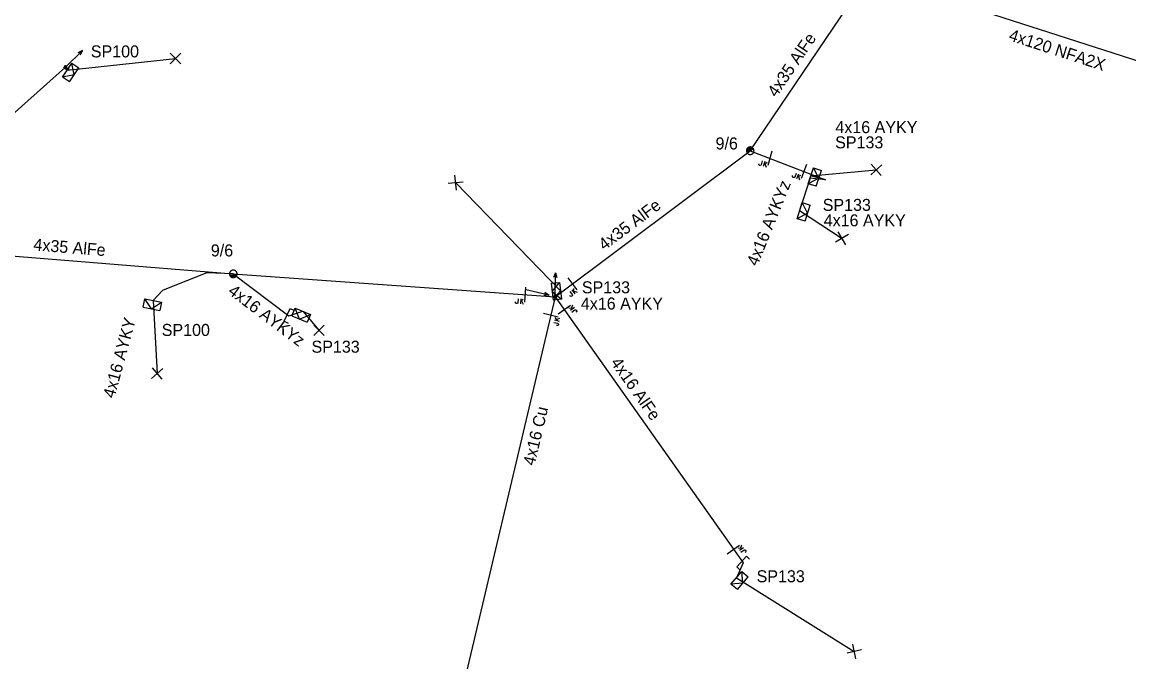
# Model space of a CAD drawing. Extents: x -788458 to -786145, y -1154772 to -1152372.
# Drawn here: x -786452.8 to -786360.6, y -1153548.2 to -1153494.9 of the extents above; entities that cross this region are included whole.
import ezdxf

# ---------------------------------------------------------------- set-up
doc = ezdxf.new("R2010")
doc.units = 0
for name, color, linetype in [('Vrstva 1', 7, 'Continuous'), ('Vrstva 12', 7, 'Continuous'), ('Vrstva 13', 7, 'Continuous'), ('Vrstva 15', 7, 'Continuous'), ('Vrstva 18', 7, 'Continuous'), ('Vrstva 2', 7, 'Continuous'), ('Vrstva 31', 7, 'Continuous'), ('Vrstva 33', 7, 'Continuous'), ('Vrstva 34', 7, 'Continuous'), ('Vrstva 4', 7, 'Continuous'), ('Vrstva 50', 7, 'Continuous'), ('Vrstva 51', 7, 'Continuous'), ('Vrstva 52', 7, 'Continuous'), ('Vrstva 53', 7, 'Continuous'), ('Vrstva 54', 7, 'Continuous'), ('Vrstva 55', 7, 'Continuous'), ('Vrstva 59', 7, 'Continuous'), ('Vrstva 9', 7, 'Continuous')]:
    doc.layers.add(name, color=color, linetype=linetype)

# ---------------------------------------------------------------- blocks, each defined once
blk = doc.blocks.new('NN440')
at = {"layer": 'Vrstva 2'}
for points in [[(0.63, 0), (0.63, 0.06), (0.62, 0.13), (0.6, 0.19), (0.58, 0.25), (0.55, 0.31), (0.51, 0.37), (0.47, 0.42), (0.42, 0.46), (0.37, 0.51), (0.32, 0.54), (0.26, 0.57), (0.2, 0.59), (0.13, 0.61), (0.07, 0.62), (0, 0.63), (-0.06, 0.62), (-0.13, 0.61), (-0.19, 0.59), (-0.26, 0.57), (-0.31, 0.54), (-0.37, 0.51), (-0.42, 0.46), (-0.47, 0.42), (-0.51, 0.37), (-0.54, 0.31), (-0.57, 0.25), (-0.6, 0.19), (-0.62, 0.13), (-0.63, 0.06), (-0.63, 0), (-0.63, -0.07), (-0.62, -0.14), (-0.6, -0.2), (-0.57, -0.26), (-0.54, -0.32), (-0.51, -0.37), (-0.47, -0.43), (-0.42, -0.47), (-0.37, -0.51), (-0.31, -0.55), (-0.26, -0.58), (-0.19, -0.6), (-0.13, -0.62), (-0.06, -0.63), (0, -0.63), (0.07, -0.63), (0.13, -0.62), (0.2, -0.6), (0.26, -0.58), (0.32, -0.55), (0.37, -0.51), (0.42, -0.47), (0.47, -0.43), (0.51, -0.37), (0.55, -0.32), (0.58, -0.26), (0.6, -0.2), (0.62, -0.14), (0.63, -0.07), (0.63, 0)], [(-0.63, 0), (0.63, 0)], [(-0.6, -0.18), (0.57, -0.18)], [(-0.51, -0.32), (0.5, -0.32)], [(-0.37, -0.47), (0.35, -0.47)]]:
    blk.add_lwpolyline(points, dxfattribs=at)
blk = doc.blocks.new('NN560')
at = {"layer": 'Vrstva 2'}
for points in [[(1.999, -0.001), (1.59, 0.141)], [(0, -0.001), (1.999, -0.001)], [(1.999, -0.001), (1.59, -0.134)]]:
    blk.add_lwpolyline(points, dxfattribs=at)
blk = doc.blocks.new('NN840')
at = {"layer": 'Vrstva 15'}
for points in [[(0.003, 0.619), (0.003, -0.631)], [(-0.745, -0.71), (-0.745, -0.66)], [(-0.73, -0.764), (-0.745, -0.71)], [(-0.657, -0.798), (-0.73, -0.764)], [(-0.627, -0.798), (-0.657, -0.798)], [(-0.558, -0.764), (-0.627, -0.798)], [(-0.538, -0.71), (-0.558, -0.764)], [(-0.538, -0.385), (-0.538, -0.71)], [(-0.332, -0.385), (-0.332, -0.798)], [(-0.332, -0.641), (-0.125, -0.385)], [(-0.263, -0.557), (-0.091, -0.798)]]:
    blk.add_lwpolyline(points, dxfattribs=at)
blk = doc.blocks.new('NN565')
at = {"layer": 'Vrstva 2'}
for points in [[(0.015, 0.528), (0.015, 2.528)], [(0.157, 0.937), (0.015, 0.528), (-0.119, 0.937)]]:
    blk.add_lwpolyline(points, dxfattribs=at)
blk = doc.blocks.new('NN800')
at = {"layer": 'Vrstva 1'}
for points in [[(-0.442, 0.442), (0.442, -0.442)], [(-0.442, -0.442), (0.442, 0.442)]]:
    blk.add_lwpolyline(points, dxfattribs=at)
blk = doc.blocks.new('NN630')
at = {"layer": 'Vrstva 9'}
for points in [[(-0.003, -0.7), (-0.703, 0)], [(-0.703, -0.7), (-0.703, 0), (0.697, 0), (0.697, -0.7)], [(-0.703, -0.7), (0.697, -0.7)], [(-0.003, -0.7), (0.697, 0)]]:
    blk.add_lwpolyline(points, dxfattribs=at)
blk = doc.blocks.new('NN500')
at = {"layer": 'Vrstva 2'}
for points in [[(0, -0.24), (0.02, -0.23), (0.05, -0.23), (0.07, -0.22), (0.09, -0.22), (0.12, -0.2), (0.14, -0.19), (0.16, -0.18), (0.17, -0.16), (0.19, -0.14), (0.2, -0.12), (0.21, -0.1), (0.22, -0.07), (0.23, -0.05), (0.23, -0.02), (0.23, 0), (0.23, 0.02), (0.23, 0.05), (0.22, 0.07), (0.21, 0.1), (0.2, 0.12), (0.19, 0.14), (0.17, 0.16), (0.16, 0.17), (0.14, 0.19), (0.12, 0.2), (0.09, 0.21), (0.07, 0.22), (0.05, 0.23), (0.02, 0.23), (0, 0.23), (-0.03, 0.23), (-0.05, 0.23), (-0.07, 0.22), (-0.1, 0.21), (-0.12, 0.2), (-0.14, 0.19), (-0.16, 0.17), (-0.18, 0.16), (-0.19, 0.14), (-0.2, 0.12), (-0.22, 0.1), (-0.22, 0.07), (-0.23, 0.05), (-0.23, 0.02), (-0.24, 0), (-0.23, -0.02), (-0.23, -0.05), (-0.22, -0.07), (-0.22, -0.1), (-0.2, -0.12), (-0.19, -0.14), (-0.18, -0.16), (-0.16, -0.18), (-0.14, -0.19), (-0.12, -0.2), (-0.1, -0.22), (-0.07, -0.22), (-0.05, -0.23), (-0.03, -0.23), (0, -0.24)], [(0, -0.24), (0.02, -0.23), (0.05, -0.23), (0.07, -0.22), (0.09, -0.22), (0.12, -0.2), (0.14, -0.19), (0.16, -0.18), (0.17, -0.16), (0.19, -0.14), (0.2, -0.12), (0.21, -0.1), (0.22, -0.07), (0.23, -0.05), (0.23, -0.02), (0.23, 0), (0.23, 0.02), (0.23, 0.05), (0.22, 0.07), (0.21, 0.1), (0.2, 0.12), (0.19, 0.14), (0.17, 0.16), (0.16, 0.17), (0.14, 0.19), (0.12, 0.2), (0.09, 0.21), (0.07, 0.22), (0.05, 0.23), (0.02, 0.23), (0, 0.23), (-0.03, 0.23), (-0.05, 0.23), (-0.07, 0.22), (-0.1, 0.21), (-0.12, 0.2), (-0.14, 0.19), (-0.16, 0.17), (-0.18, 0.16), (-0.19, 0.14), (-0.2, 0.12), (-0.22, 0.1), (-0.22, 0.07), (-0.23, 0.05), (-0.23, 0.02), (-0.24, 0), (-0.23, -0.02), (-0.23, -0.05), (-0.22, -0.07), (-0.22, -0.1), (-0.2, -0.12), (-0.19, -0.14), (-0.18, -0.16), (-0.16, -0.18), (-0.14, -0.19), (-0.12, -0.2), (-0.1, -0.22), (-0.07, -0.22), (-0.05, -0.23), (-0.03, -0.23), (0, -0.24)], [(0, -0.21), (0.02, -0.2), (0.04, -0.2), (0.06, -0.2), (0.08, -0.19), (0.1, -0.18), (0.12, -0.17), (0.14, -0.15), (0.15, -0.14), (0.16, -0.12), (0.18, -0.1), (0.19, -0.08), (0.19, -0.06), (0.2, -0.04), (0.2, -0.02), (0.2, 0), (0.2, 0.02), (0.2, 0.04), (0.19, 0.06), (0.19, 0.08), (0.18, 0.1), (0.16, 0.12), (0.15, 0.14), (0.14, 0.15), (0.12, 0.17), (0.1, 0.18), (0.08, 0.19), (0.06, 0.19), (0.04, 0.2), (0.02, 0.2), (0, 0.2), (-0.02, 0.2), (-0.04, 0.2), (-0.06, 0.19), (-0.08, 0.19), (-0.1, 0.18), (-0.12, 0.17), (-0.14, 0.15), (-0.15, 0.14), (-0.17, 0.12), (-0.18, 0.1), (-0.19, 0.08), (-0.2, 0.06), (-0.2, 0.04), (-0.21, 0.02), (-0.21, 0), (-0.21, -0.02), (-0.2, -0.04), (-0.2, -0.06), (-0.19, -0.08), (-0.18, -0.1), (-0.17, -0.12), (-0.15, -0.14), (-0.14, -0.15), (-0.12, -0.17), (-0.1, -0.18), (-0.08, -0.19), (-0.06, -0.2), (-0.04, -0.2), (-0.02, -0.2), (0, -0.21)], [(0, -0.18), (0.02, -0.18), (0.04, -0.17), (0.05, -0.17), (0.07, -0.16), (0.09, -0.15), (0.1, -0.14), (0.12, -0.13), (0.13, -0.12), (0.14, -0.1), (0.15, -0.09), (0.16, -0.07), (0.17, -0.05), (0.17, -0.04), (0.17, -0.02), (0.17, 0), (0.17, 0.02), (0.17, 0.04), (0.17, 0.05), (0.16, 0.07), (0.15, 0.09), (0.14, 0.1), (0.13, 0.12), (0.12, 0.13), (0.1, 0.14), (0.09, 0.15), (0.07, 0.16), (0.05, 0.17), (0.04, 0.17), (0.02, 0.17), (0, 0.18), (-0.02, 0.17), (-0.04, 0.17), (-0.06, 0.17), (-0.07, 0.16), (-0.09, 0.15), (-0.1, 0.14), (-0.12, 0.13), (-0.13, 0.12), (-0.14, 0.1), (-0.15, 0.09), (-0.16, 0.07), (-0.17, 0.05), (-0.17, 0.04), (-0.18, 0.02), (-0.18, 0), (-0.18, -0.02), (-0.17, -0.04), (-0.17, -0.05), (-0.16, -0.07), (-0.15, -0.09), (-0.14, -0.1), (-0.13, -0.12), (-0.12, -0.13), (-0.1, -0.14), (-0.09, -0.15), (-0.07, -0.16), (-0.06, -0.17), (-0.04, -0.17), (-0.02, -0.18), (0, -0.18)], [(0, -0.15), (0.01, -0.15), (0.03, -0.14), (0.04, -0.14), (0.06, -0.13), (0.07, -0.13), (0.08, -0.12), (0.1, -0.11), (0.11, -0.1), (0.12, -0.09), (0.13, -0.07), (0.13, -0.06), (0.14, -0.05), (0.14, -0.03), (0.14, -0.02), (0.14, 0), (0.14, 0.01), (0.14, 0.03), (0.14, 0.04), (0.13, 0.06), (0.13, 0.07), (0.12, 0.09), (0.11, 0.1), (0.1, 0.11), (0.08, 0.12), (0.07, 0.13), (0.06, 0.13), (0.04, 0.14), (0.03, 0.14), (0.01, 0.14), (0, 0.15), (-0.02, 0.14), (-0.03, 0.14), (-0.05, 0.14), (-0.06, 0.13), (-0.07, 0.13), (-0.09, 0.12), (-0.1, 0.11), (-0.11, 0.1), (-0.12, 0.09), (-0.13, 0.07), (-0.13, 0.06), (-0.14, 0.04), (-0.14, 0.03), (-0.15, 0.01), (-0.15, 0), (-0.15, -0.02), (-0.14, -0.03), (-0.14, -0.05), (-0.13, -0.06), (-0.13, -0.07), (-0.12, -0.09), (-0.11, -0.1), (-0.1, -0.11), (-0.09, -0.12), (-0.07, -0.13), (-0.06, -0.13), (-0.05, -0.14), (-0.03, -0.14), (-0.02, -0.15), (0, -0.15)], [(0, -0.12), (0.01, -0.12), (0.02, -0.11), (0.03, -0.11), (0.05, -0.11), (0.06, -0.1), (0.07, -0.09), (0.08, -0.09), (0.09, -0.08), (0.09, -0.07), (0.1, -0.06), (0.11, -0.05), (0.11, -0.04), (0.11, -0.02), (0.11, -0.01), (0.12, 0), (0.11, 0.01), (0.11, 0.02), (0.11, 0.04), (0.11, 0.05), (0.1, 0.06), (0.09, 0.07), (0.09, 0.08), (0.08, 0.09), (0.07, 0.09), (0.06, 0.1), (0.05, 0.11), (0.03, 0.11), (0.02, 0.11), (0.01, 0.12), (0, 0.12), (-0.01, 0.12), (-0.03, 0.11), (-0.04, 0.11), (-0.05, 0.11), (-0.06, 0.1), (-0.07, 0.09), (-0.08, 0.09), (-0.09, 0.08), (-0.1, 0.07), (-0.1, 0.06), (-0.11, 0.05), (-0.11, 0.04), (-0.12, 0.02), (-0.12, 0.01), (-0.12, 0), (-0.12, -0.01), (-0.12, -0.02), (-0.11, -0.04), (-0.11, -0.05), (-0.1, -0.06), (-0.1, -0.07), (-0.09, -0.08), (-0.08, -0.09), (-0.07, -0.09), (-0.06, -0.1), (-0.05, -0.11), (-0.04, -0.11), (-0.03, -0.11), (-0.01, -0.12), (0, -0.12)], [(0, -0.09), (0.01, -0.09), (0.02, -0.09), (0.03, -0.08), (0.03, -0.08), (0.04, -0.08), (0.05, -0.07), (0.06, -0.07), (0.06, -0.06), (0.07, -0.05), (0.07, -0.04), (0.08, -0.04), (0.08, -0.03), (0.08, -0.02), (0.09, -0.01), (0.09, 0), (0.09, 0.01), (0.08, 0.02), (0.08, 0.03), (0.08, 0.03), (0.07, 0.04), (0.07, 0.05), (0.06, 0.06), (0.06, 0.06), (0.05, 0.07), (0.04, 0.07), (0.03, 0.08), (0.03, 0.08), (0.02, 0.08), (0.01, 0.09), (0, 0.09), (-0.01, 0.09), (-0.02, 0.08), (-0.03, 0.08), (-0.04, 0.08), (-0.04, 0.07), (-0.05, 0.07), (-0.06, 0.06), (-0.07, 0.06), (-0.07, 0.05), (-0.08, 0.04), (-0.08, 0.03), (-0.08, 0.03), (-0.09, 0.02), (-0.09, 0.01), (-0.09, 0), (-0.09, -0.01), (-0.09, -0.02), (-0.08, -0.03), (-0.08, -0.04), (-0.08, -0.04), (-0.07, -0.05), (-0.07, -0.06), (-0.06, -0.07), (-0.05, -0.07), (-0.04, -0.08), (-0.04, -0.08), (-0.03, -0.08), (-0.02, -0.09), (-0.01, -0.09), (0, -0.09)], [(0, -0.06), (0, -0.06), (0.01, -0.06), (0.02, -0.05), (0.02, -0.05), (0.03, -0.05), (0.03, -0.05), (0.04, -0.04), (0.04, -0.04), (0.05, -0.03), (0.05, -0.03), (0.05, -0.02), (0.05, -0.02), (0.05, -0.01), (0.06, -0.01), (0.06, 0), (0.06, 0.01), (0.05, 0.01), (0.05, 0.02), (0.05, 0.02), (0.05, 0.03), (0.05, 0.03), (0.04, 0.04), (0.04, 0.04), (0.03, 0.05), (0.03, 0.05), (0.02, 0.05), (0.02, 0.05), (0.01, 0.06), (0, 0.06), (0, 0.06), (-0.01, 0.06), (-0.01, 0.06), (-0.02, 0.05), (-0.02, 0.05), (-0.03, 0.05), (-0.03, 0.05), (-0.04, 0.04), (-0.04, 0.04), (-0.05, 0.03), (-0.05, 0.03), (-0.05, 0.02), (-0.06, 0.02), (-0.06, 0.01), (-0.06, 0.01), (-0.06, 0), (-0.06, -0.01), (-0.06, -0.01), (-0.06, -0.02), (-0.05, -0.02), (-0.05, -0.03), (-0.05, -0.03), (-0.04, -0.04), (-0.04, -0.04), (-0.03, -0.05), (-0.03, -0.05), (-0.02, -0.05), (-0.02, -0.05), (-0.01, -0.06), (-0.01, -0.06), (0, -0.06)], [(0, -0.03), (0, -0.03), (0, -0.03), (0.01, -0.03), (0.01, -0.03), (0.01, -0.02), (0.02, -0.02), (0.02, -0.02), (0.02, -0.02), (0.02, -0.02), (0.02, -0.01), (0.02, -0.01), (0.03, -0.01), (0.03, -0.01), (0.03, 0), (0.03, 0), (0.03, 0), (0.03, 0.01), (0.03, 0.01), (0.02, 0.01), (0.02, 0.01), (0.02, 0.02), (0.02, 0.02), (0.02, 0.02), (0.02, 0.02), (0.01, 0.02), (0.01, 0.02), (0.01, 0.03), (0, 0.03), (0, 0.03), (0, 0.03), (0, 0.03), (-0.01, 0.03), (-0.01, 0.03), (-0.01, 0.02), (-0.02, 0.02), (-0.02, 0.02), (-0.02, 0.02), (-0.02, 0.02), (-0.02, 0.02), (-0.03, 0.01), (-0.03, 0.01), (-0.03, 0.01), (-0.03, 0.01), (-0.03, 0), (-0.03, 0), (-0.03, 0), (-0.03, -0.01), (-0.03, -0.01), (-0.03, -0.01), (-0.03, -0.01), (-0.02, -0.02), (-0.02, -0.02), (-0.02, -0.02), (-0.02, -0.02), (-0.02, -0.02), (-0.01, -0.03), (-0.01, -0.03), (-0.01, -0.03), (0, -0.03), (0, -0.03)], [(0.23, 0), (0.7, 0)]]:
    blk.add_lwpolyline(points, dxfattribs=at)
blk = doc.blocks.new('NN510')
at = {"layer": 'Vrstva 2'}
blk.add_lwpolyline([(0.001, 0.002), (0.001, 0.939)], dxfattribs=at)
blk = doc.blocks.new('NN515')
at = {"layer": 'Vrstva 2'}
for points in [[(-0.59, 0.176), (0.591, 0.176)], [(-0.59, 0.176), (-0.59, -0.179)], [(0.591, 0.176), (0.591, -0.179)]]:
    blk.add_lwpolyline(points, dxfattribs=at)

msp = doc.modelspace()

# ---------------------------------------------------------------- linework, layer by layer
at = {"layer": 'Vrstva 1'}
for points in [[(-786392.1, -1153505.61), (-786382.055, -1153490.74)], [(-786408.35, -1153517.77), (-786392.1, -1153505.61)], [(-786489.69, -1153518.84), (-786465.68, -1153513.4), (-786435.17, -1153515.87), (-786408.35, -1153517.77)], [(-786408.35, -1153517.77), (-786417.32, -1153555.73)]]:
    msp.add_lwpolyline(points, dxfattribs=at)
at = {"layer": 'Vrstva 4'}
msp.add_lwpolyline([(-786408.35, -1153517.77), (-786392.69, -1153539.96), (-786393.25, -1153541.19)], dxfattribs=at)
at = {"layer": 'Vrstva 50'}
msp.add_lwpolyline([(-786381.77, -1153491.026), (-786354.19, -1153499.92), (-786327.4, -1153511.45), (-786300.99, -1153523.12), (-786278.65, -1153526.63), (-786247.26, -1153533.29)], dxfattribs=at)
at = {"layer": 'Vrstva 52'}
for points in [[(-786392.1, -1153505.61), (-786385.83, -1153508.03)], [(-786385.83, -1153508.03), (-786387.116, -1153507.895), (-786387.99, -1153510.6)], [(-786385.83, -1153508.03), (-786387.05, -1153507.69)], [(-786435.17, -1153515.87), (-786437.38, -1153515.79), (-786440.593, -1153517.07), (-786441.07, -1153517.26), (-786441.84, -1153518.1)], [(-786408.35, -1153517.77), (-786407.91, -1153517.28)]]:
    msp.add_lwpolyline(points, dxfattribs=at)
at = {"layer": 'Vrstva 54'}
for points in [[(-786465.68, -1153513.4), (-786449.16, -1153498.66), (-786449, -1153498.89)], [(-786435.17, -1153515.87), (-786430.53, -1153519.36), (-786429.38, -1153518.99)]]:
    msp.add_lwpolyline(points, dxfattribs=at)
at = {"layer": 'Vrstva 59'}
for points in [[(-786449, -1153498.89), (-786439.99, -1153497.92)], [(-786387.05, -1153507.69), (-786381.6, -1153507.2)], [(-786407.91, -1153517.28), (-786416.64, -1153508.28)], [(-786387.99, -1153510.6), (-786384.45, -1153512.91)], [(-786441.84, -1153518.1), (-786441.52, -1153524.17)], [(-786429.38, -1153518.99), (-786428.03, -1153520.574)], [(-786393.25, -1153541.19), (-786383.43, -1153547.34)]]:
    msp.add_lwpolyline(points, dxfattribs=at)

# ---------------------------------------------------------------- block references
at = {"layer": 'Vrstva 13'}
for name, p, rotation in [('NN560', (-786449.16, -1153498.66), 44.177608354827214), ('NN510', (-786385.83, -1153508.03), 72.85435277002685), ('NN560', (-786408.35, -1153517.77), 89.59178605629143), ('NN565', (-786408.35, -1153517.77), 77.00544445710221), ('NN515', (-786430.53, -1153519.36), 65.55088885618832), ('NN515', (-786392.69, -1153539.96), 47.64990833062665)]:
    msp.add_blockref(name, p, dxfattribs=dict(at, rotation=rotation))
for name, p, xscale, yscale, rotation in [('NN500', (-786449.16, -1153498.66), 0.5, 0.5, -26.22699992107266), ('NN440', (-786392.1, -1153505.61), 0.5, 0.5, -147.57503332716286), ('NN440', (-786435.17, -1153515.87), 0.49999999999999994, 0.4999999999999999, -3.4574889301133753), ('NN500', (-786408.35, -1153517.77), 0.5, 0.5000000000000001, 89.08499996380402)]:
    msp.add_blockref(name, p, dxfattribs=dict(at, xscale=xscale, yscale=yscale, rotation=rotation))
at = {"layer": 'Vrstva 18'}
for p, rotation in [((-786390.476, -1153506.237), -15.720481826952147), ((-786387.638, -1153507.332), -21.104839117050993), ((-786406.925, -1153516.704), 36.807791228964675), ((-786410.867, -1153517.592), -4.052214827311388), ((-786407.594, -1153518.842), 125.01068611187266), ((-786408.711, -1153519.297), 76.70480845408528), ((-786393.507, -1153538.843), 125.01068616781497)]:
    msp.add_blockref('NN840', p, dxfattribs=dict(at, rotation=rotation))
at = {"layer": 'Vrstva 31'}
for p, rotation in [((-786449, -1153498.89), 56.437256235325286), ((-786387.05, -1153507.69), 71.95883043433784), ((-786387.99, -1153510.6), 72.98271418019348), ((-786407.91, -1153517.28), -83.88449645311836), ((-786441.84, -1153518.1), -11.142889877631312), ((-786429.38, -1153518.99), -22.873665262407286), ((-786393.25, -1153541.19), 49.63546343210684)]:
    msp.add_blockref('NN630', p, dxfattribs=dict(at, rotation=rotation))
at = {"layer": 'Vrstva 34'}
for p, rotation in [((-786439.99, -1153497.92), -179.71398327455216), ((-786381.6, -1153507.2), 177.14854729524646), ((-786416.64, -1153508.28), 140.5530167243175), ((-786384.45, -1153512.91), 165.18993606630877), ((-786441.52, -1153524.17), -94.48448607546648), ((-786383.43, -1153547.34), 147.5325527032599)]:
    msp.add_blockref('NN800', p, dxfattribs=dict(at, rotation=rotation))
msp.add_blockref('NN800', (-786428.03, -1153520.574), dxfattribs=at)

# ---------------------------------------------------------------- texts
at = {"layer": 'Vrstva 12'}
for p in [(-786394.991, -1153505.502), (-786437.039, -1153514.417)]:
    msp.add_text('9/6', height=1, dxfattribs=at).set_placement(p)
at = {"layer": 'Vrstva 2'}
for s, rotation, p in [('4x35 AlFe', 55.976, (-786389.927, -1153501.216)), ('4x35 AlFe', 36.808, (-786404.269, -1153513.962)), ('4x35 AlFe', 355.372, (-786451.849, -1153513.909)), ('4x16 Cu', 76.705, (-786410.076, -1153531.906))]:
    msp.add_text(s, height=1, rotation=rotation, dxfattribs=at).set_placement(p)
at = {"layer": 'Vrstva 33'}
for s, p in [('SP100', (-786447.04, -1153497.833)), ('SP133', (-786385.03, -1153505.411)), ('SP133', (-786386.064, -1153510.623)), ('SP133', (-786406.13, -1153517.491)), ('SP100', (-786441.132, -1153521.042)), ('SP133', (-786428.652, -1153522.439)), ('SP133', (-786391.571, -1153541.565))]:
    msp.add_text(s, height=1, dxfattribs=at).set_placement(p)
at = {"layer": 'Vrstva 51'}
msp.add_text('4x120 NFA2X', height=1, rotation=341.966, dxfattribs=at).set_placement((-786370.633, -1153496.39))
at = {"layer": 'Vrstva 53'}
for s, rotation, p in [('4x16 AYKYz', 67.969, (-786391.509, -1153515.29)), ('4x16 AlFe', 305.011, (-786403.775, -1153523.259))]:
    msp.add_text(s, height=1, rotation=rotation, dxfattribs=at).set_placement(p)
at = {"layer": 'Vrstva 54'}
for p in [(-786385.009, -1153504.145), (-786385.98, -1153511.91), (-786406.214, -1153518.841)]:
    msp.add_text('4x16 AYKY', height=1, dxfattribs=at).set_placement(p)
msp.add_text('4x16 AYKY', height=1, rotation=74.772, dxfattribs=at).set_placement((-786445.081, -1153526.286))
at = {"layer": 'Vrstva 55'}
msp.add_text('4x16 AYKYz', height=1, rotation=323.051, dxfattribs=at).set_placement((-786435.689, -1153517.469))

doc.saveas('drawing.dxf')
